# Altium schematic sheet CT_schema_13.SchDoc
size 278 x 170 mm
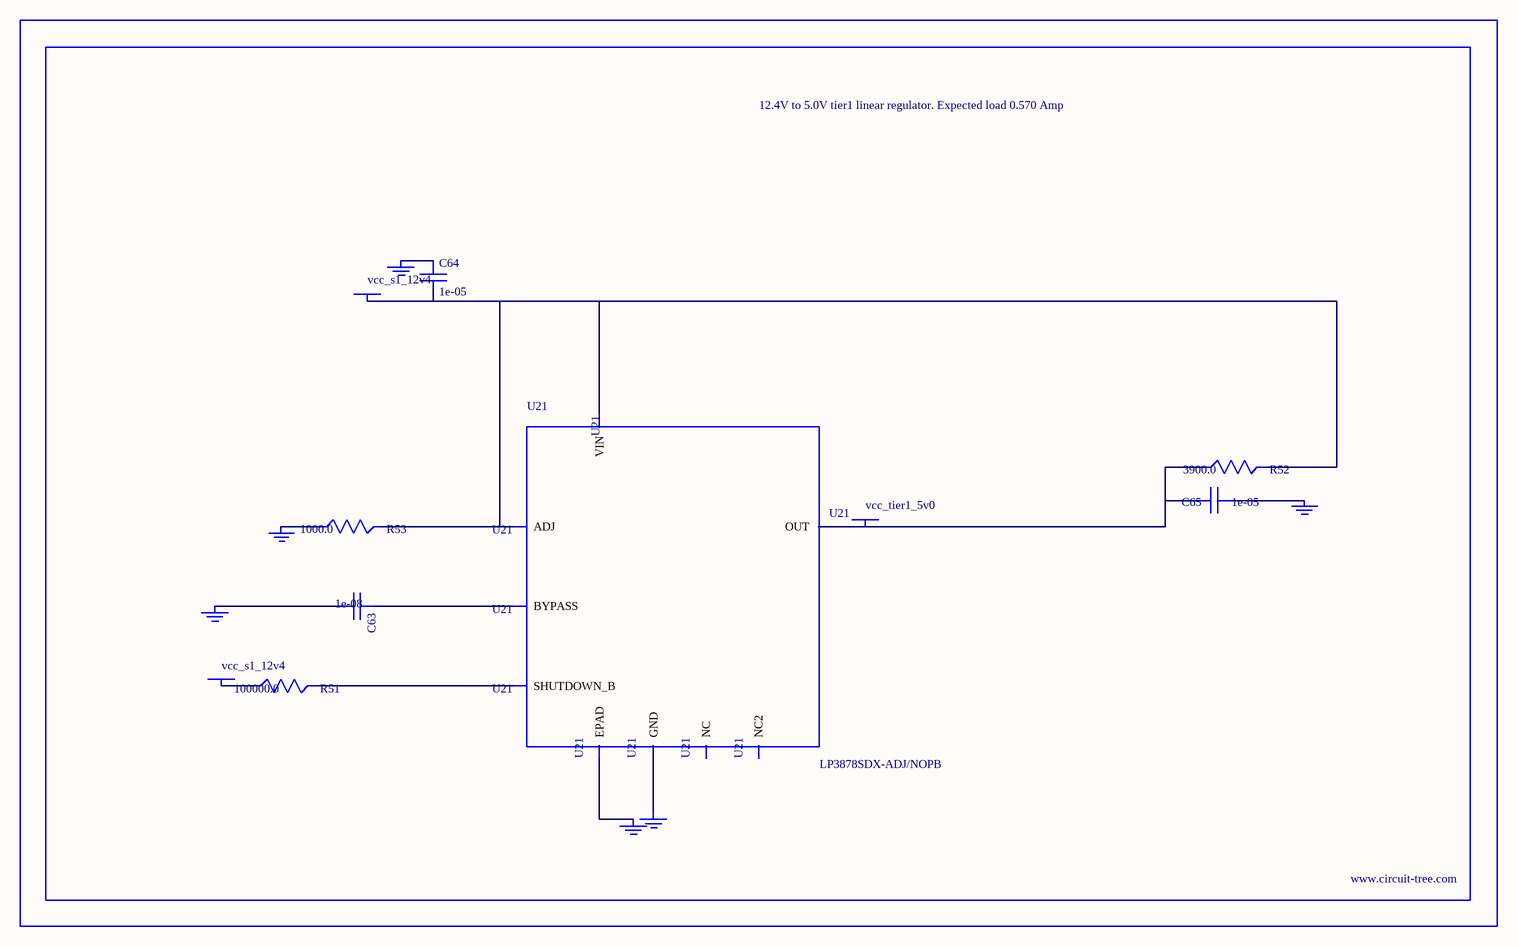
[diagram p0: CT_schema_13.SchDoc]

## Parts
BORDER12  (no value)
C63  1e-08  [C0402]
C64  1e-05  [C1210]
C65  1e-05  [C1210]
GND_INSTANCE_12_0  (no value)
GND_INSTANCE_12_1  (no value)
GND_INSTANCE_12_2  (no value)
GND_INSTANCE_12_3  (no value)
GND_INSTANCE_12_4  (no value)
GND_INSTANCE_12_5  (no value)
POWER_INSTANCE_12_0  vcc_s1_12v4
POWER_INSTANCE_12_1  vcc_s1_12v4
POWER_INSTANCE_12_2  vcc_tier1_5v0
R51  100000.0  [R0603]
R52  3900.0  [R0603]
R53  1000.0  [R0603]
U21  LP3878SDX-ADJ/NOPB  [WSON-8]

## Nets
NetC63_1: C63.1 U21.1(BYPASS)
NetC63_2: C63.2 GND_INSTANCE_12_0.0(GND)
NetC64_1: C64.1 GND_INSTANCE_12_1.0(GND)
NetC64_2: C64.2 POWER_INSTANCE_12_0.0(PWR) R52.2 R53.2 U21.4(VIN) U21.6(ADJ)
NetC65_1: C65.1 GND_INSTANCE_12_2.0(GND)
NetC65_2: C65.2 POWER_INSTANCE_12_2.0(PWR) R52.1 U21.5(OUT)
NetGND_INSTANCE_12_3_0: GND_INSTANCE_12_3.0(GND) R53.1
NetGND_INSTANCE_12_4_0: GND_INSTANCE_12_4.0(GND) U21.PAD(EPAD)
NetGND_INSTANCE_12_5_0: GND_INSTANCE_12_5.0(GND) U21.3(GND)
NetPOWER_INSTANCE_12_1_0: POWER_INSTANCE_12_1.0(PWR) R51.1
NetR51_2: R51.2 U21.8(SHUTDOWN_B)

Not connected (* = marked no-connect by the designer): U21 2(NC) 7(NC2)

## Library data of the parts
BORDER12 = BORDER_PAGE12
C63 = C0402C103K3RAC
C64 = C1210C106K5PACTU
C65 = GRM32DR61E106MA12L
GND_INSTANCE_12_0-GND_INSTANCE_12_5 = GND
POWER_INSTANCE_12_0-POWER_INSTANCE_12_2 = PWR
R51 = RC0603JR-07100KL
R52 = RC0603JR-073K9L
R53 = RC0603JR-071KL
